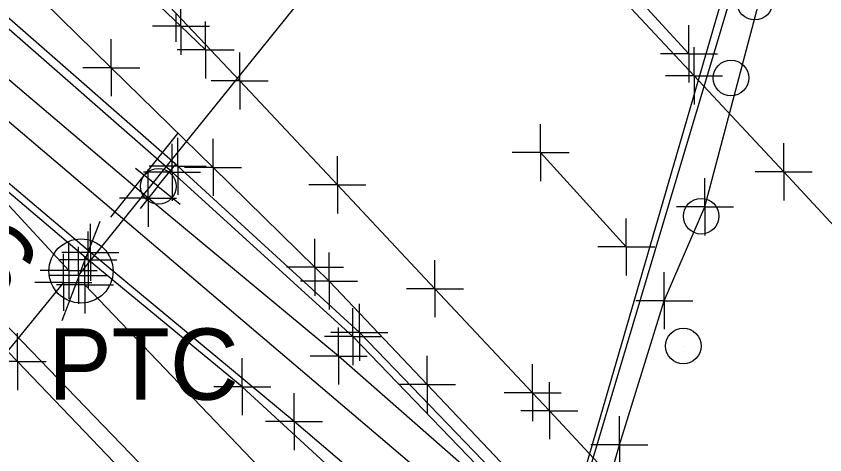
# Model space of a CAD drawing. Extents: x 0 to 1944463, y 0 to 420651.
# Drawn here: x 1943051.6 to 1943108.3, y 417546.3 to 417577.1 of the extents above; entities that cross this region are included whole.
import ezdxf

# ---------------------------------------------------------------- set-up
doc = ezdxf.new("R2010")
doc.units = 0
for name, color, linetype in [('SUR - DRG - Bridges', 7, 'Continuous'), ('SUR - DTM - Breaklines', 7, 'Continuous'), ('SUR - DTM - Breaklines - Points - Locators', 7, 'Continuous'), ('SUR - DTM - Spot Points - Locators', 7, 'Continuous'), ('SUR - NON-TRAN - Features', 7, 'Continuous'), ('SUR - NON-TRAN - Features - Points - Locators', 7, 'Continuous'), ('SUR - TR-CTRL - Pavement Marking', 7, 'Continuous'), ('SUR - TR-CTRL - Pavement Marking - Points - Locators', 7, 'Continuous'), ('SUR - TR-CTRL - Signs and Devices', 7, 'Continuous'), ('SUR - TR-CTRL - Signs and Devices - Points - Locators', 7, 'Continuous'), ('SUR - TRAN - Features', 7, 'Continuous'), ('SUR - TRAN - Features - Points - Locators', 7, 'Continuous'), ('SUR - TRAN - Roadside Barriers', 7, 'Continuous'), ('SUR - TRAN - Roadside Barriers - Points - Locators', 7, 'Continuous'), ('SUR - UTL - Fiber Optic Cable (Underground)', 7, 'Continuous'), ('SUR - UTL - Overhead Wire Crossings', 7, 'Continuous'), ('SUR - UTL - Overhead Wire Crossings - Points - Locators', 7, 'Continuous'), ('SUR - UTL - Poles and Miscellaneous', 7, 'Continuous'), ('SUR - UTL - Poles and Miscellaneous Text', 7, 'Continuous'), ('SUR - VEG - Features Text', 7, 'Continuous')]:
    doc.layers.add(name, color=color, linetype=linetype)

msp = doc.modelspace()

# ---------------------------------------------------------------- linework, layer by layer
at = {"layer": 'SUR - DRG - Bridges'}
msp.add_lwpolyline([(1943194.586, 417417.65), (1943160.612, 417454.166), (1943126.96, 417490.097), (1943087.359, 417532.419), (1943088.24, 417533.281), (1943102.062, 417579.551), (1943115.41, 417624.415), (1943114.938, 417624.906), (1943115.852, 417625.619), (1943152.828, 417586.155), (1943187.702, 417548.755), (1943222.943, 417511.078), (1943222.064, 417510.2)], close=True, dxfattribs=at)
at = {"layer": 'SUR - DTM - Breaklines'}
for points in [[(1943086.971, 417542.441), (1943075.211, 417554.629), (1943062.523, 417566.148), (1943025.76, 417598.308), (1942997.463, 417625.18), (1942961.642, 417658.671), (1942931.319, 417684.435), (1942886.042, 417718.77), (1942847.117, 417744.736), (1942804.588, 417770.285), (1942795.222, 417775.523)], [(1942925.069, 417677.067), (1942949.401, 417656.72), (1942968.648, 417639.301), (1943001.406, 417607.095), (1943034.84, 417572.033), (1943085.56, 417519.524), (1943094.963, 417509.455)], [(1943087.03, 417524.51), (1943089.19, 417528.64), (1943089.52, 417528.79), (1943092.32, 417538.36), (1943091.52, 417538.73), (1943093.91, 417547.05), (1943097.06, 417557.15), (1943099.91, 417563.73), (1943104.27, 417580.24), (1943106.63, 417588.26), (1943107.36, 417588.66), (1943110.36, 417597.71), (1943114.56, 417612.95), (1943118.31, 417630.27)], [(1943090, 417540.17), (1943101.8, 417580.66), (1943113.3, 417618.05)]]:
    msp.add_lwpolyline(points, dxfattribs=at)
at = {"layer": 'SUR - DTM - Breaklines - Points - Locators'}
for p, q in [((1943062.523, 417566.148), (1943062.523, 417568.148)), ((1943062.523, 417566.148), (1943060.523, 417566.148)), ((1943062.523, 417566.148), (1943064.523, 417566.148)), ((1943062.523, 417566.148), (1943062.523, 417564.148)), ((1943099.91, 417563.73), (1943099.91, 417565.73)), ((1943099.91, 417563.73), (1943097.91, 417563.73)), ((1943099.91, 417563.73), (1943101.91, 417563.73)), ((1943099.91, 417563.73), (1943099.91, 417561.73)), ((1943097.06, 417557.15), (1943097.06, 417559.15)), ((1943097.06, 417557.15), (1943095.06, 417557.15)), ((1943097.06, 417557.15), (1943099.06, 417557.15)), ((1943097.06, 417557.15), (1943097.06, 417555.15)), ((1943075.211, 417554.629), (1943075.211, 417556.629)), ((1943075.211, 417554.629), (1943073.211, 417554.629)), ((1943075.211, 417554.629), (1943077.211, 417554.629)), ((1943075.211, 417554.629), (1943075.211, 417552.629)), ((1943093.91, 417547.05), (1943093.91, 417549.05)), ((1943093.91, 417547.05), (1943091.91, 417547.05)), ((1943093.91, 417547.05), (1943095.91, 417547.05)), ((1943093.91, 417547.05), (1943093.91, 417545.05))]:
    msp.add_line(p, q, dxfattribs=at)
at = {"layer": 'SUR - DTM - Spot Points - Locators'}
for p, q in [((1943101.75, 417572.75), (1943101.75, 417572.75)), ((1943099.66, 417563.06), (1943099.66, 417563.06)), ((1943098.41, 417553.96), (1943098.41, 417553.96))]:
    msp.add_line(p, q, dxfattribs=at)
for centre in [(1943103.409, 417578.081), (1943101.739, 417572.761), (1943099.649, 417563.071), (1943098.399, 417553.971)]:
    msp.add_circle(centre, 1.25, dxfattribs=at)
at = {"layer": 'SUR - NON-TRAN - Features'}
msp.add_lwpolyline([(1943087.191, 417532.975), (1943067.445, 417551.113), (1943056.633, 417560.008), (1943019.762, 417591.28), (1943005.17, 417604.135), (1943000.177, 417608.233), (1942990.385, 417617.734), (1942954.627, 417651.698), (1942925.373, 417676.361)], dxfattribs=at)
at = {"layer": 'SUR - NON-TRAN - Features - Points - Locators'}
for p, q in [((1943056.633, 417560.008), (1943056.633, 417562.008)), ((1943056.633, 417560.008), (1943054.633, 417560.008)), ((1943056.633, 417560.008), (1943058.633, 417560.008)), ((1943056.633, 417560.008), (1943056.633, 417558.008)), ((1943067.445, 417551.113), (1943067.445, 417553.113)), ((1943067.445, 417551.113), (1943065.445, 417551.113)), ((1943067.445, 417551.113), (1943069.445, 417551.113)), ((1943067.445, 417551.113), (1943067.445, 417549.113))]:
    msp.add_line(p, q, dxfattribs=at)
at = {"layer": 'SUR - TR-CTRL - Pavement Marking'}
for points in [[(1943049.034, 417591.82), (1943055.909, 417584.558), (1943062.785, 417577.297), (1943067.272, 417572.558), (1943074.12, 417565.271), (1943080.969, 417557.985), (1943087.818, 417550.698), (1943089.003, 417549.436), (1943095.803, 417542.105), (1943102.604, 417534.773), (1943109.404, 417527.441), (1943116.204, 417520.109), (1943117.838, 417518.348), (1943124.638, 417511.016), (1943131.439, 417503.684), (1943138.239, 417496.352), (1943145.039, 417489.02), (1943147.729, 417486.12), (1943154.51, 417478.77), (1943161.291, 417471.42), (1943168.072, 417464.071)], [(1943092.393, 417581.427), (1943098.793, 417574.452)], [(1943051.102, 417580.476), (1943058.249, 417573.482), (1943065.396, 417566.488), (1943072.543, 417559.494), (1943073.532, 417558.526), (1943080.415, 417551.273), (1943087.299, 417544.019), (1943094.182, 417536.765), (1943098.067, 417532.671), (1943104.874, 417525.345), (1943111.681, 417518.02), (1943118.488, 417510.694), (1943125.295, 417503.368), (1943132.102, 417496.043), (1943135.725, 417492.143), (1943142.532, 417484.817), (1943149.339, 417477.491), (1943156.146, 417470.166), (1943158.866, 417467.239), (1943165.702, 417459.94)], [(1943092.328, 417580.219), (1943099.155, 417572.913), (1943105.446, 417566.18), (1943112.254, 417558.855), (1943119.061, 417551.53), (1943125.869, 417544.204), (1943132.676, 417536.879), (1943139.483, 417529.554), (1943146.241, 417522.283), (1943153.048, 417514.958), (1943159.856, 417507.633), (1943166.663, 417500.307), (1943173.47, 417492.982), (1943174.548, 417491.823), (1943181.301, 417484.447), (1943188.054, 417477.072), (1943194.807, 417469.696), (1943199.772, 417464.274)], [(1943088.379, 417567.527), (1943094.391, 417560.916)]]:
    msp.add_lwpolyline(points, dxfattribs=at)
at = {"layer": 'SUR - TR-CTRL - Pavement Marking - Points - Locators'}
for p, q in [((1943098.793, 417574.452), (1943098.793, 417576.452)), ((1943058.249, 417573.482), (1943058.249, 417575.482)), ((1943099.155, 417572.913), (1943099.155, 417574.913)), ((1943098.793, 417574.452), (1943096.793, 417574.452)), ((1943098.793, 417574.452), (1943100.793, 417574.452)), ((1943098.793, 417574.452), (1943098.793, 417572.452)), ((1943058.249, 417573.482), (1943056.249, 417573.482)), ((1943058.249, 417573.482), (1943060.249, 417573.482)), ((1943058.249, 417573.482), (1943058.249, 417571.482)), ((1943099.155, 417572.913), (1943097.155, 417572.913)), ((1943099.155, 417572.913), (1943101.155, 417572.913)), ((1943099.155, 417572.913), (1943099.155, 417570.913)), ((1943088.379, 417567.527), (1943088.379, 417569.527)), ((1943065.396, 417566.488), (1943065.396, 417568.488)), ((1943105.446, 417566.18), (1943105.446, 417568.18)), ((1943088.379, 417567.527), (1943086.379, 417567.527)), ((1943088.379, 417567.527), (1943090.379, 417567.527)), ((1943088.379, 417567.527), (1943088.379, 417565.527)), ((1943065.396, 417566.488), (1943063.396, 417566.488)), ((1943065.396, 417566.488), (1943067.396, 417566.488)), ((1943065.396, 417566.488), (1943065.396, 417564.488)), ((1943105.446, 417566.18), (1943103.446, 417566.18)), ((1943105.446, 417566.18), (1943107.446, 417566.18)), ((1943105.446, 417566.18), (1943105.446, 417564.18)), ((1943094.391, 417560.916), (1943094.391, 417562.916)), ((1943072.543, 417559.494), (1943072.543, 417561.494)), ((1943094.391, 417560.916), (1943092.391, 417560.916)), ((1943094.391, 417560.916), (1943096.391, 417560.916)), ((1943094.391, 417560.916), (1943094.391, 417558.916)), ((1943073.532, 417558.526), (1943073.532, 417560.526)), ((1943072.543, 417559.494), (1943070.543, 417559.494)), ((1943072.543, 417559.494), (1943074.543, 417559.494)), ((1943072.543, 417559.494), (1943072.543, 417557.494)), ((1943073.532, 417558.526), (1943071.532, 417558.526)), ((1943073.532, 417558.526), (1943075.532, 417558.526)), ((1943073.532, 417558.526), (1943073.532, 417556.526)), ((1943080.415, 417551.273), (1943080.415, 417553.273)), ((1943080.415, 417551.273), (1943078.415, 417551.273)), ((1943080.415, 417551.273), (1943082.415, 417551.273)), ((1943080.415, 417551.273), (1943080.415, 417549.273))]:
    msp.add_line(p, q, dxfattribs=at)
at = {"layer": 'SUR - TR-CTRL - Signs and Devices'}
msp.add_line((1943058.223, 417563.005), (1943062.91, 417568.86), dxfattribs=at)
msp.add_circle((1943061.556, 417565.168), 1.25, dxfattribs=at)
at = {"layer": 'SUR - TR-CTRL - Signs and Devices - Points - Locators'}
for q in [(1943059.961, 417566.417), (1943062.773, 417566.729), (1943060.273, 417563.606), (1943063.084, 417563.917)]:
    msp.add_line((1943061.523, 417565.167), q, dxfattribs=at)
at = {"layer": 'SUR - TRAN - Features'}
for p, q in [((1943063.133, 417576.386), (1943063.133, 417578.386)), ((1943062.785, 417577.297), (1943062.785, 417575.297)), ((1943064.872, 417574.729), (1943064.872, 417576.729)), ((1943063.133, 417576.386), (1943061.133, 417576.386)), ((1943063.133, 417576.386), (1943065.133, 417576.386)), ((1943063.133, 417576.386), (1943063.133, 417574.386)), ((1943064.872, 417574.729), (1943062.872, 417574.729)), ((1943064.872, 417574.729), (1943066.872, 417574.729)), ((1943064.872, 417574.729), (1943064.872, 417572.729)), ((1943067.272, 417572.558), (1943067.272, 417574.558)), ((1943067.272, 417572.558), (1943065.272, 417572.558)), ((1943067.272, 417572.558), (1943069.272, 417572.558)), ((1943067.272, 417572.558), (1943067.272, 417570.558)), ((1943074.12, 417565.271), (1943074.12, 417567.271)), ((1943074.12, 417565.271), (1943072.12, 417565.271)), ((1943074.12, 417565.271), (1943076.12, 417565.271)), ((1943074.12, 417565.271), (1943074.12, 417563.271)), ((1943080.969, 417557.985), (1943080.969, 417559.985)), ((1943080.969, 417557.985), (1943078.969, 417557.985)), ((1943080.969, 417557.985), (1943082.969, 417557.985)), ((1943080.969, 417557.985), (1943080.969, 417555.985)), ((1943087.818, 417550.698), (1943087.818, 417552.698)), ((1943089.003, 417549.436), (1943089.003, 417551.436)), ((1943087.818, 417550.698), (1943085.818, 417550.698)), ((1943087.818, 417550.698), (1943089.818, 417550.698)), ((1943087.818, 417550.698), (1943087.818, 417548.698)), ((1943089.003, 417549.436), (1943087.003, 417549.436)), ((1943089.003, 417549.436), (1943091.003, 417549.436)), ((1943089.003, 417549.436), (1943089.003, 417547.436))]:
    msp.add_line(p, q, dxfattribs=at)
for points in [[(1943087.394, 417542.772), (1943075.666, 417554.93), (1943062.916, 417566.57), (1943026.148, 417598.738), (1942997.824, 417625.573), (1942962.083, 417659.135), (1942931.717, 417684.819), (1942886.624, 417719.066), (1942847.443, 417745.259), (1942804.756, 417770.865), (1942795.632, 417775.977)], [(1943088.058, 417533.458), (1943083.95, 417537.719), (1943071.074, 417548.672), (1943056.792, 417560.53), (1943019.915, 417591.688), (1942990.429, 417618.512), (1942955.076, 417651.996), (1942925.728, 417676.871), (1942880.991, 417710.724), (1942841.949, 417736.86), (1942799.694, 417762.25), (1942785.094, 417769.761), (1942769.186, 417774.3), (1942763.842, 417772.965), (1942759.218, 417770.8), (1942756.131, 417769.011), (1942750.267, 417764.38), (1942746.064, 417757.407), (1942742.493, 417740.651), (1942741.733, 417732.524), (1942737.14, 417690.548), (1942733.569, 417661.203)], [(1943089.939, 417539.879), (1943087.376, 417542.435), (1943087.013, 417542.026), (1943074.207, 417553.267), (1943060.831, 417564.334), (1943023.676, 417595.881), (1942994.415, 417622.433), (1942959.135, 417655.824), (1942929.13, 417681.51), (1942884.161, 417715.389)], [(1943004.247, 417632.935), (1943011.481, 417626.031), (1943016.025, 417621.693), (1943023.182, 417614.709), (1943030.339, 417607.724), (1943034.176, 417603.979), (1943041.415, 417597.081), (1943048.654, 417590.183), (1943055.894, 417583.284), (1943063.133, 417576.386), (1943064.872, 417574.729)]]:
    msp.add_lwpolyline(points, dxfattribs=at)
at = {"layer": 'SUR - TRAN - Features - Points - Locators'}
for p, q in [((1943062.916, 417566.57), (1943062.916, 417568.57)), ((1943060.831, 417564.334), (1943060.831, 417566.334)), ((1943062.916, 417566.57), (1943060.916, 417566.57)), ((1943062.916, 417566.57), (1943064.916, 417566.57)), ((1943062.916, 417566.57), (1943062.916, 417564.57)), ((1943060.831, 417564.334), (1943058.831, 417564.334)), ((1943060.831, 417564.334), (1943062.831, 417564.334)), ((1943060.831, 417564.334), (1943060.831, 417562.334)), ((1943056.792, 417560.53), (1943056.792, 417562.53)), ((1943056.792, 417560.53), (1943054.792, 417560.53)), ((1943056.792, 417560.53), (1943058.792, 417560.53)), ((1943056.792, 417560.53), (1943056.792, 417558.53)), ((1943075.666, 417554.93), (1943075.666, 417556.93)), ((1943074.207, 417553.267), (1943074.207, 417555.267)), ((1943075.666, 417554.93), (1943073.666, 417554.93)), ((1943075.666, 417554.93), (1943077.666, 417554.93)), ((1943075.666, 417554.93), (1943075.666, 417552.93)), ((1943074.207, 417553.267), (1943072.207, 417553.267)), ((1943074.207, 417553.267), (1943076.207, 417553.267)), ((1943074.207, 417553.267), (1943074.207, 417551.267)), ((1943071.074, 417548.672), (1943071.074, 417550.672)), ((1943071.074, 417548.672), (1943069.074, 417548.672)), ((1943071.074, 417548.672), (1943073.074, 417548.672)), ((1943071.074, 417548.672), (1943071.074, 417546.672))]:
    msp.add_line(p, q, dxfattribs=at)
at = {"layer": 'SUR - TRAN - Roadside Barriers'}
msp.add_lwpolyline([(1943094.4, 417508.843), (1943084.523, 417518.605), (1943051.67, 417552.881), (1943047.229, 417557.471), (1943031.956, 417573.542), (1943015.955, 417590.762), (1942975.623, 417631.424), (1942967.434, 417639.312), (1942942.743, 417660.22), (1942924.496, 417676.578)], dxfattribs=at)
at = {"layer": 'SUR - TRAN - Roadside Barriers - Points - Locators'}
for q in [(1943051.67, 417554.881), (1943049.67, 417552.881), (1943053.67, 417552.881), (1943051.67, 417550.881)]:
    msp.add_line((1943051.67, 417552.881), q, dxfattribs=at)
at = {"layer": 'SUR - UTL - Fiber Optic Cable (Underground)'}
msp.add_lwpolyline([(1943675.935, 416874.811), (1943301.532, 417291.453), (1943229.017, 417377.593), (1943204.769, 417412.08), (1943079.474, 417545.559), (1943001.447, 417611.824), (1942943.851, 417666.04), (1942875.969, 417717.873), (1942785.445, 417773.544), (1942671.047, 417813.855), (1942647.996, 417834.422), (1942364.461, 417940.541)], dxfattribs=at)
at = {"layer": 'SUR - UTL - Overhead Wire Crossings'}
for points in [[(1943055.95, 417558.92), (1943121.57, 417640.17)], [(1943055.269, 417559.269), (1942997.456, 417621.828)], [(1943054.888, 417558.43), (1942932.946, 417408.978)], [(1943056.401, 417558.259), (1943199.988, 417408.257)]]:
    msp.add_lwpolyline(points, dxfattribs=at)
at = {"layer": 'SUR - UTL - Overhead Wire Crossings - Points - Locators'}
for p, q in [((1943055.269, 417559.269), (1943055.269, 417561.269)), ((1943055.95, 417558.92), (1943055.95, 417560.92)), ((1943054.888, 417558.43), (1943054.888, 417560.43)), ((1943056.401, 417558.259), (1943056.401, 417560.259)), ((1943055.269, 417559.269), (1943053.269, 417559.269)), ((1943055.95, 417558.92), (1943053.95, 417558.92)), ((1943055.269, 417559.269), (1943057.269, 417559.269)), ((1943055.269, 417559.269), (1943055.269, 417557.269)), ((1943055.95, 417558.92), (1943057.95, 417558.92)), ((1943055.95, 417558.92), (1943055.95, 417556.92)), ((1943054.888, 417558.43), (1943052.888, 417558.43)), ((1943054.888, 417558.43), (1943056.888, 417558.43)), ((1943054.888, 417558.43), (1943054.888, 417556.43)), ((1943056.401, 417558.259), (1943054.401, 417558.259)), ((1943056.401, 417558.259), (1943058.401, 417558.259)), ((1943056.401, 417558.259), (1943056.401, 417556.259))]:
    msp.add_line(p, q, dxfattribs=at)
at = {"layer": 'SUR - UTL - Poles and Miscellaneous'}
for q in [(1943057.464, 417562.734), (1943054.783, 417555.73)]:
    msp.add_line((1943056.124, 417559.232), q, dxfattribs=at)
msp.add_circle((1943056.124, 417559.232), 2.25, dxfattribs=at)

# ---------------------------------------------------------------- texts
at = {"layer": 'SUR - UTL - Poles and Miscellaneous Text'}
msp.add_text('PTC', height=5, dxfattribs=at).set_placement((1943053.82, 417550.201))
at = {"layer": 'SUR - VEG - Features Text'}
msp.add_text('GRASS', height=5, rotation=315.4738, dxfattribs=at).set_placement((1943033.381, 417573.02))

doc.saveas('drawing.dxf')
